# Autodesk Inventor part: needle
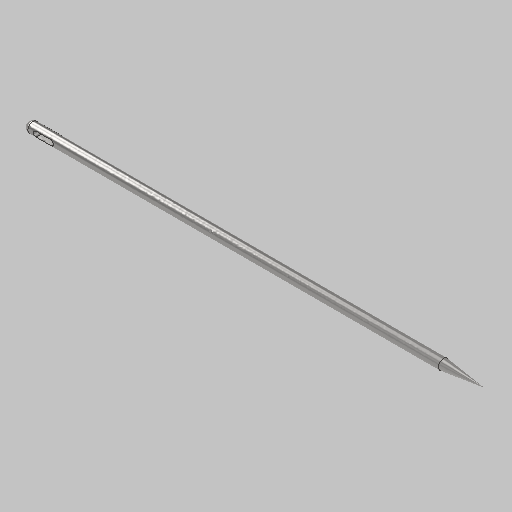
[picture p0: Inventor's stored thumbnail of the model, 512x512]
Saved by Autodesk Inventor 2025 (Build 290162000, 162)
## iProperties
Created: 2025-01
Part Number: needle
Material: Steel, Galvanized
Document SubType Name: Modeling
Designer: dansp
Density: 7.85 g/cm^3
Appearance: Galvanized
Mass: 0.252857 g
Surface Area: 1.37232 cm^2
Volume: 0.0322111 cm^3
Author: dansp
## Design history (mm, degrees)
sketch "Sketch1"
  geometry: L1 (0, 0.6)-(0, -0.1) reference; L2 (-9, 0)-(54, 0) reference; L3 (0, 0)-(0, 0.5); L4 (0, 0.5)-(45, 0.5); L5 (45, 0.5)-(45, 0); L6 (45, 0)-(41, 0.5)
  constraints: 8 end point, 3 point on line, 1 horizontal, 1 perpendicular
  dimensions: "d0" = 1 diameter of L4 L2; "d1" = 4 horizontal distance of L5.end L6.end; "d2" = 45 distance of L3.end L4.end
revolve "Revolution1" sketch "Sketch1" stored, may be unused: angle "d3" = 90 deg
sketch "Sketch2"
  geometry: L1 (1.25, 0)-(2.75, 0); L2 (1.25, -0.25)-(2.75, -0.25); L3 (2.75, 0.25)-(1.25, 0.25); L4 (0, 0.7)-(0, -0.7) reference; L5 (-9, 0)-(54, 0) reference; A1 r 0.25 centre (1.25, 0) between (1.25, 0.25) and (1.25, -0.25); A2 r 0.25 centre (2.75, 0) between (2.75, -0.25) and (2.75, 0.25); 4 further points
  constraints: 8 end point, 6 point on circle, 4 tangent, 2 centre point, 1 horizontal, 1 midpoint, 1 parallel, 1 point on line
  dimensions: "d4" = 2 distance of point (1, 0) point (3, 0); "d5" = 1 distance from line of point (1, 0) L4; "d6" = 0.5 distance between parallel lines of L2 L3
extrude "Extrusion1" cut sketch "Sketch2" extent not by distance; stored distance "d7" = 0; taper "d8" = 0 deg
fillet "Fillet1" dims "d9" = 0.5
body "Solid1"
